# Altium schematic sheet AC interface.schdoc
size 425 x 297 mm
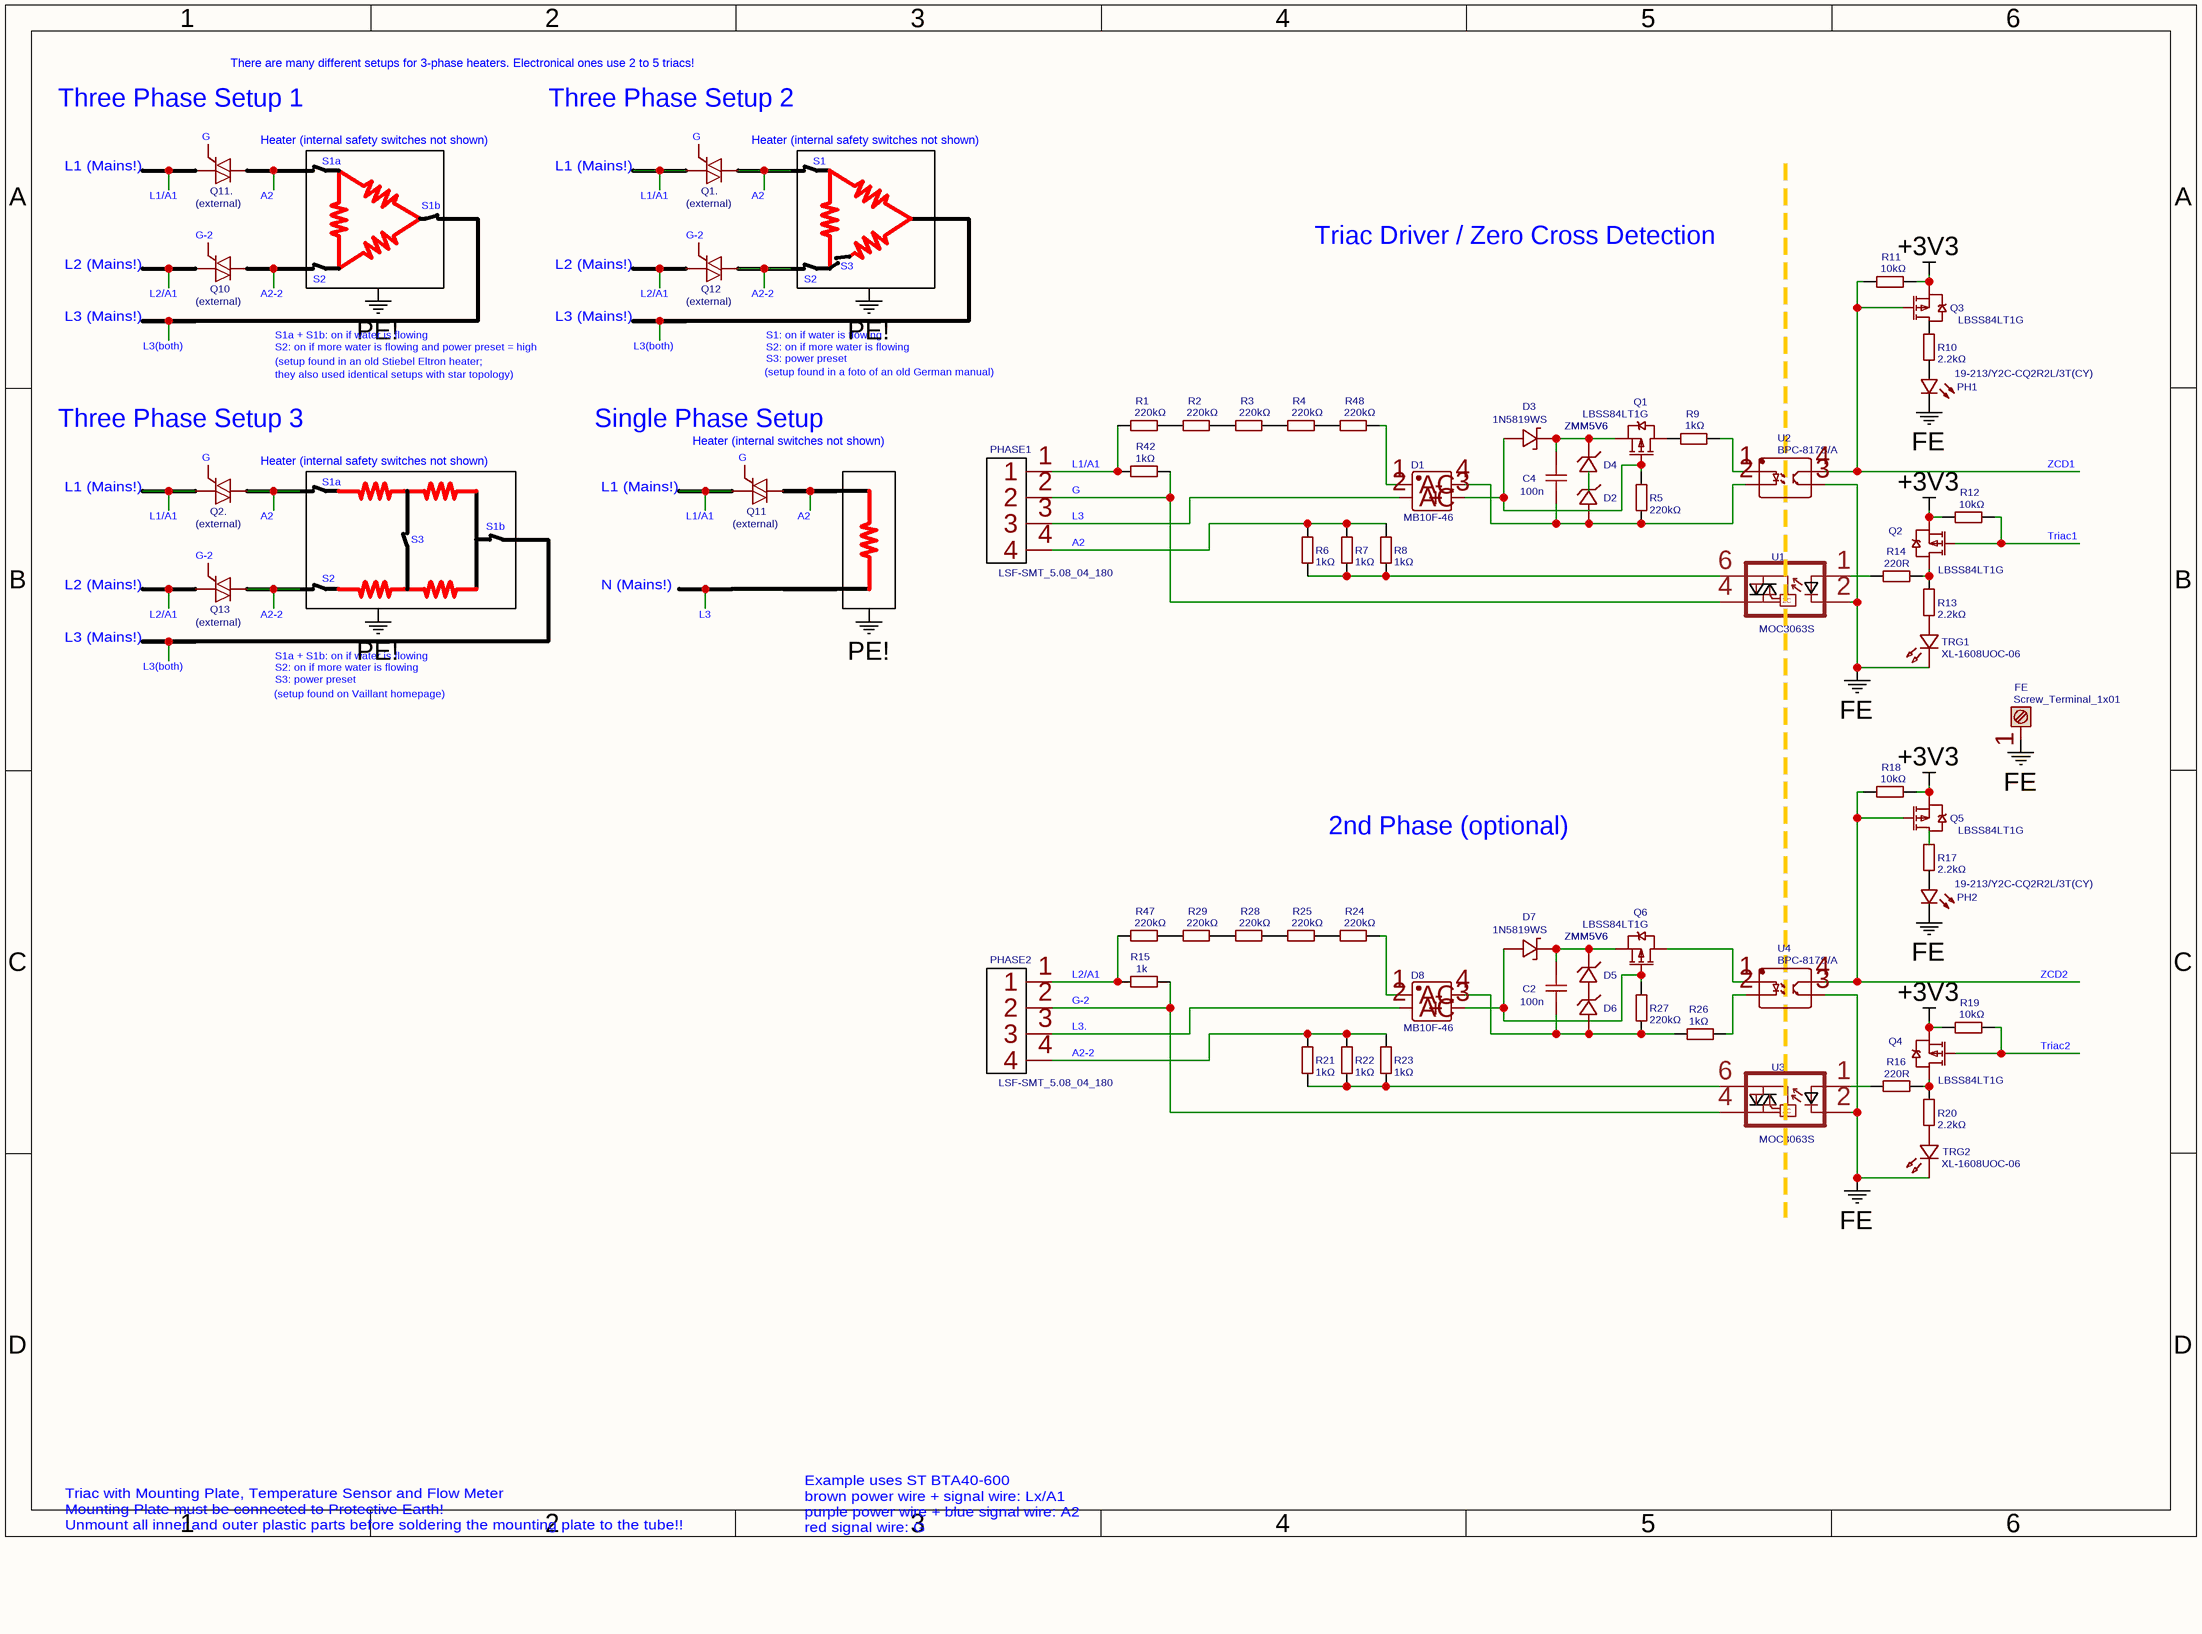
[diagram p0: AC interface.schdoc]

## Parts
C2  100n  [C0603]
C4  100n  [C0603]
D1  MB10F-46  [MBF_L4.8-W3.9-P2.50-LS6.7-BL]
D2  ZMM5V6  [LL-34_L3.5-W1.5-RD]
D3  1N5819WS  [SOD-323_L1.8-W1.3-LS2.5-RD]
D4  ZMM5V6  [LL-34_L3.5-W1.5-RD]
D5  ZMM5V6  [LL-34_L3.5-W1.5-RD]
D6  ZMM5V6  [LL-34_L3.5-W1.5-RD]
D7  1N5819WS  [SOD-323_L1.8-W1.3-LS2.5-RD]
D8  MB10F-46  [MBF_L4.8-W3.9-P2.50-LS6.7-BL]
FE  Screw_Terminal_1x01  [640454-2P]
PH1  19-213/Y2C-CQ2R2L/3T(CY)  [LED0603-R-RD]
PH2  19-213/Y2C-CQ2R2L/3T(CY)  [LED0603-R-RD]
PHASE1  LSF-SMT_5.08_04_180  [LSF-SMT_5.08_04_180]
PHASE2  LSF-SMT_5.08_04_180  [LSF-SMT_5.08_04_180]
Q1  LBSS84LT1G  [SOT-23_L2.9-W1.3-P1.90-LS2.4-BR]
Q1.  (external)  [BT136]
Q2  LBSS84LT1G  [SOT-23_L2.9-W1.3-P1.90-LS2.4-BR]
Q2.  (external)  [BT136]
Q3  LBSS84LT1G  [SOT-23_L2.9-W1.3-P1.90-LS2.4-BR]
Q4  LBSS84LT1G  [SOT-23_L2.9-W1.3-P1.90-LS2.4-BR]
Q5  LBSS84LT1G  [SOT-23_L2.9-W1.3-P1.90-LS2.4-BR]
Q6  LBSS84LT1G  [SOT-23_L2.9-W1.3-P1.90-LS2.4-BR]
Q10  (external)  [BT136]
Q11  (external)  [BT136]
Q11.  (external)  [BT136]
Q12  (external)  [BT136]
Q13  (external)  [BT136]
R1  220kΩ  [R0805]
R2  220kΩ  [R0805]
R3  220kΩ  [R0805]
R4  220kΩ  [R0805]
R5  220kΩ  [R0805]
R6  1kΩ  [R0603]
R7  1kΩ  [R0603]
R8  1kΩ  [R0603]
R9  1kΩ  [R0603]
R10  2.2kΩ  [R0603]
R11  10kΩ  [R0603]
R12  10kΩ  [R0603]
R13  2.2kΩ  [R0603]
R14  220R  [R0603]
R15  1k  [R0603]
R16  220R  [R0603]
R17  2.2kΩ  [R0603]
R18  10kΩ  [R0603]
R19  10kΩ  [R0603]
R20  2.2kΩ  [R0603]
R21  1kΩ  [R0603]
R22  1kΩ  [R0603]
R23  1kΩ  [R0603]
R24  220kΩ  [R0805]
R25  220kΩ  [R0805]
R26  1kΩ  [R0603]
R27  220kΩ  [R0805]
R28  220kΩ  [R0805]
R29  220kΩ  [R0805]
R42  1kΩ  [R0603]
R47  220kΩ  [R0805]
R48  220kΩ  [R0805]
TRG1  XL-1608UOC-06  [LED0603-R-RD_ORANGE]
TRG2  XL-1608UOC-06  [LED0603-R-RD_ORANGE]
U1  MOC3063S  [DIP8SMD]
U2  BPC-817S/A  [SOP-4_L6.5-W4.6-P2.54-LS10.2-BR]
U3  MOC3063S  [DIP8SMD]
U4  BPC-817S/A  [SOP-4_L6.5-W4.6-P2.54-LS10.2-BR]

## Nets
+3V3: Q2.2(S) Q3.2(S) Q4.2(S) Q5.2(S) R11.2 R12.1 R18.2 R19.1
FE: FE.1 PH1.2(C) PH2.2(C) TRG1.2(A) TRG2.2(A) U1.2(K) U2.3(E) U3.2(K) U4.3(E)
A2: PHASE1.4 R6.1 R7.1 R8.1
A2-2: PHASE2.4 R21.1 R22.1 R23.1
G: PHASE1.2 R42.1 U1.4(T2)
G-2: PHASE2.2 R15.1 U3.4(T2)
L1/A1: PHASE1.1 R1.1 R42.2
L2/A1: PHASE2.1 R15.2 R47.1
L3: D1.2(AC) PHASE1.3
L3.: D8.2(AC) PHASE2.3
Triac1: Q2.1(G) R12.2
Triac2: Q4.1(G) R19.2
ZCD1: Q3.1(G) R11.1 U2.4(C)
ZCD2: Q5.1(G) R18.1 U4.4(C)
NetC2_1: C2.1 D6.2(A) D8.4(-) R26.1 R27.1
NetC2_2: C2.2 D5.1(C) D7.1(C) Q6.2(S)
NetC4_1: C4.1 D1.4(-) D2.2(A) R5.1 U2.2(C)
NetC4_2: C4.2 D3.1(C) D4.1(C) Q1.2(S)
NetD1_1: D1.1(AC) R48.2
NetD1_3: D1.3(+) D3.2(A) Q1.1(G) R5.2
NetD2_1: D2.1(C) D4.2(A)
NetD5_2: D5.2(A) D6.1(C)
NetD7_2: D7.2(A) D8.3(+) Q6.1(G) R27.2
NetD8_1: D8.1(AC) R24.2
NetPH1_1: PH1.1(A) R10.1
NetPH2_1: PH2.1(A) R17.1
NetQ1_3: Q1.3(D) R9.2
NetQ2_3: Q2.3(D) R13.2 R14.2
NetQ3_3: Q3.3(D) R10.2
NetQ4_3: Q4.3(D) R16.2 R20.2
NetQ5_3: Q5.3(D) R17.2
NetQ6_3: Q6.3(D) U4.1(A)
NetR1_2: R1.2 R2.1
NetR2_2: R2.2 R3.1
NetR3_2: R3.2 R4.1
NetR4_2: R4.2 R48.1
NetR6_2: R6.2 R7.2 R8.2 U1.6(T1)
NetR9_1: R9.1 U2.1(A)
NetR13_1: R13.1 TRG1.1(K)
NetR14_1: R14.1 U1.1(A)
NetR16_1: R16.1 U3.1(A)
NetR20_1: R20.1 TRG2.1(K)
NetR21_2: R21.2 R22.2 R23.2 U3.6(T1)
NetR24_1: R24.1 R25.2
NetR25_1: R25.1 R28.2
NetR26_2: R26.2 U4.2(C)
NetR28_1: R28.1 R29.2
NetR29_1: R29.1 R47.2

Not connected (* = marked no-connect by the designer): Q1. 1(M1) 2(M2) 3(G); Q2. 1(M1) 2(M2) 3(G); Q10 1(M1) 2(M2) 3(G); Q11 1(M1) 2(M2) 3(G); Q11. 1(M1) 2(M2) 3(G); Q12 1(M1) 2(M2) 3(G); Q13 1(M1) 2(M2) 3(G)

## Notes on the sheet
- (near Q11.) Three Phase Setup 1
- There are many different setups for 3-phase heaters. Electronical ones use 2 to 5 triacs!
- (near Q1.) Three Phase Setup 2
- L1 (Mains!)
- (near Q11.) Heater (internal safety switches not shown)
- S1a
- (near Q1.) Heater (internal safety switches not shown)
- S1
- S1b
- Triac Driver / Zero Cross Detection
- L2 (Mains!)
- S2
- S3
- L3 (Mains!)
- S1a + S1b: on if water is flowing
- S2: on if more water is flowing and power preset = high
- (setup found in an old Stiebel Eltron heater;
- they also used identical setups with star topology)
- (setup found in a foto of an old German manual)
- S2: on if more water is flowing
- S1: on if water is flowing
- S3: power preset
- (near Q2.) Three Phase Setup 3
- (near Q11) Single Phase Setup
- (near Q11) Heater (internal switches not shown)
- (near Q2.) Heater (internal safety switches not shown)
- N (Mains!)
- (setup found on Vaillant homepage)
- 2nd Phase (optional)
- Triac with Mounting Plate, Temperature Sensor and Flow Meter
  Mounting Plate must be connected to Protective Earth!
  Unmount all inner and outer plastic parts before soldering the mounting plate to the tube!!
- Example uses ST BTA40-600
  brown power wire + signal wire: Lx/A1
  purple power wire + blue signal wire: A2
  red signal wire: G
- Labels drawn without touching a wire or pin: A2, A2-2, G, G-2, L1/A1, L2/A1, L3, L3(both), PE!

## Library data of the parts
C2 C4 = 100n: nameAlias: Capacitance; Contributor: LCSC
D1 D8 = MB10F-46: BOM_Manufacturer: MDD
D2 D4-D6 = ZMM5V6: BOM_Manufacturer: SEMTECH
D3 D7 = 1N5819WS: BOM_Manufacturer: Guangdong Hottech; Contributor: LCSC
FE = Screw_Terminal_1x01: Contributor: KiCAD
PH1 PH2 = 19-213/Y2C-CQ2R2L/3T(CY): BOM_Manufacturer: EVERLIGHT
PHASE1 PHASE2 = LSF-SMT_5.08_04_180: Contributor: BBEloBaelz
Q1-Q6 = LBSS84LT1G: BOM_Manufacturer: LRC
Q1. Q2. Q10 Q11 Q11. Q12 Q13 = (external): BOM_Manufacturer: CJ; Contributor: goleniec
R1-R5 R24 R25 R27-R29 R47 R48 = 220kΩ: BOM_Manufacturer: UniOhm; BOM_Manufacturer Part: 0805W8F2203T5E; nameAlias: Resistance; Resistance (Ohms): 220K
R6-R9 R21-R23 R26 R42 = 1kΩ: BOM_Manufacturer: UniOhm; BOM_Manufacturer Part: 0603WAF1001T5E; nameAlias: Resistance; Resistance (Ohms): 1K
R10 R13 R17 R20 = 2.2kΩ: BOM_Manufacturer: UniOhm; BOM_Manufacturer Part: 0603WAF2201T5E; nameAlias: Resistance; Resistance (Ohms): 2.2K
R11 R12 R18 R19 = 10kΩ: BOM_Manufacturer: UniOhm; BOM_Manufacturer Part: 0603WAF1002T5E; nameAlias: Resistance; Resistance (Ohms): 10K
R14 R16 = 220R: nameAlias: Resistance (Ohms)
R15 = 1k: nameAlias: Resistance (Ohms)
TRG1 TRG2 = XL-1608UOC-06: BOM_Manufacturer: XINGLIGHT(成兴光); Contributor: lcsc
U1 U3 = MOC3063S: description: Optotriac in DIP and SMD; Contributor: SparkFun
U2 U4 = BPC-817S/A: BOM_Manufacturer: Bright LED Elec; Contributor: LCSC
